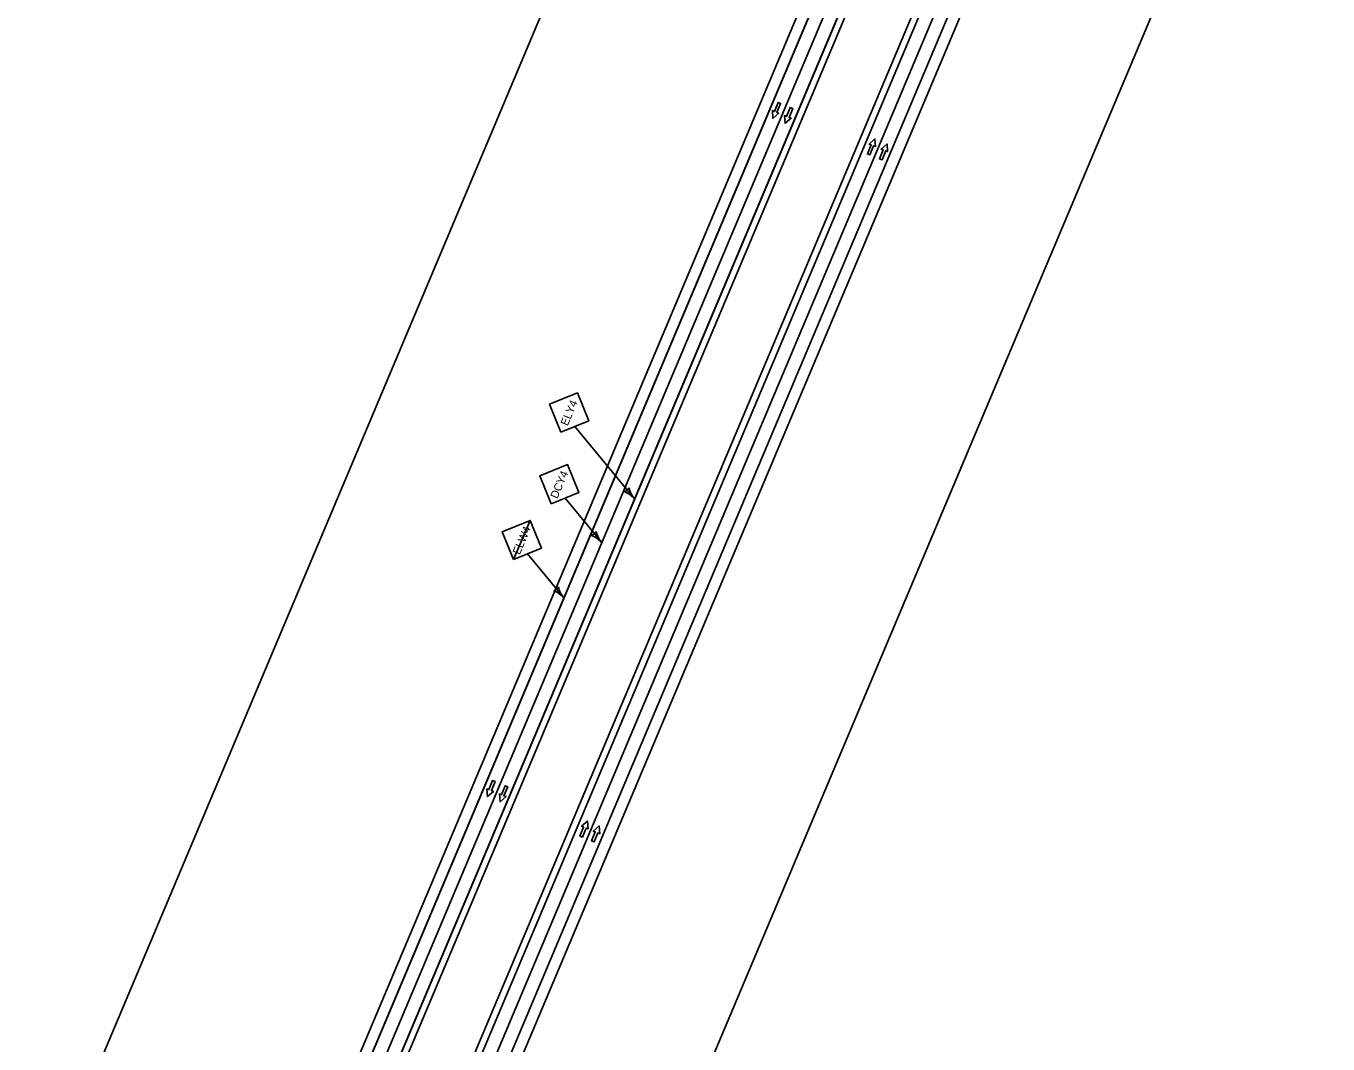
# Model space of a CAD drawing. Extents: x 14104283 to 14129344, y 8637090 to 8673339.
# Drawn here: x 14108941 to 14110109, y 8645697 to 8646611 of the extents above; entities that cross this region are included whole.
import ezdxf

# ---------------------------------------------------------------- set-up
doc = ezdxf.new("R2010")
doc.units = 0
for name, color, linetype in [('Cell', 7, 'Continuous'), ('Default', 7, 'Continuous'), ('dsnNonPlotable', 7, 'Continuous'), ('dsnPaintExistingBrokenLaneLineWhite', 7, 'Continuous'), ('dsnPaintExistingEdgeLineRightWhite', 7, 'Continuous'), ('dsnPaintPlaceBrokenLineWhite', 7, 'Continuous'), ('dsnPaintPlaceEdgeLineLeftYellow', 7, 'Continuous'), ('dsnPaintPlaceEdgeLineRightWhite', 7, 'Continuous'), ('dsnShadingPaved', 7, 'Continuous'), ('dsnStdLabel', 7, 'Continuous'), ('dsnStgShadingPrevPav', 7, 'Continuous')]:
    doc.layers.add(name, color=color, linetype=linetype)

msp = doc.modelspace()

# ---------------------------------------------------------------- linework, layer by layer
at = {"layer": 'Cell'}
for points in [[(14109615.6, 8646542.8), (14109617.9, 8646541.9), (14109614.6, 8646533.8), (14109616.3, 8646533.1), (14109611.1, 8646528.5), (14109610.6, 8646535.5), (14109612.3, 8646534.7)], [(14109626.5, 8646538.4), (14109628.8, 8646537.5), (14109625.5, 8646529.4), (14109627.3, 8646528.7), (14109622, 8646524.1), (14109621.5, 8646531), (14109623.2, 8646530.3)], [(14109698.1, 8646495.8), (14109695.8, 8646496.7), (14109699.1, 8646504.8), (14109697.3, 8646505.5), (14109702.6, 8646510.1), (14109703.1, 8646503.2), (14109701.4, 8646503.9)], [(14109709, 8646491.3), (14109706.7, 8646492.2), (14109710, 8646500.3), (14109708.2, 8646501), (14109713.5, 8646505.6), (14109714, 8646498.7), (14109712.3, 8646499.4)], [(14109359.3, 8645933.9), (14109361.6, 8645933), (14109358.3, 8645924.9), (14109360.1, 8645924.2), (14109354.8, 8645919.6), (14109354.3, 8645926.5), (14109356, 8645925.8)], [(14109370.7, 8645929.3), (14109373, 8645928.3), (14109369.6, 8645920.2), (14109371.4, 8645919.5), (14109366.1, 8645914.9), (14109365.6, 8645921.9), (14109367.3, 8645921.2)], [(14109440, 8645883.1), (14109437.7, 8645884.1), (14109441, 8645892.2), (14109439.3, 8645892.9), (14109444.5, 8645897.5), (14109445.1, 8645890.5), (14109443.3, 8645891.2)], [(14109450.5, 8645878.9), (14109448.2, 8645879.8), (14109451.5, 8645887.9), (14109449.8, 8645888.6), (14109455.1, 8645893.2), (14109455.6, 8645886.2), (14109453.8, 8645886.9)]]:
    msp.add_lwpolyline(points, close=True, dxfattribs=at)
for points in [[(14109612.3, 8646534.7), (14109610.6, 8646535.5), (14109611.1, 8646528.5), (14109616.3, 8646533.1), (14109614.6, 8646533.8), (14109617.9, 8646541.9), (14109615.6, 8646542.8), (14109612.3, 8646534.7)], [(14109623.2, 8646530.3), (14109621.5, 8646531), (14109622, 8646524.1), (14109627.3, 8646528.7), (14109625.5, 8646529.4), (14109628.8, 8646537.5), (14109626.5, 8646538.4), (14109623.2, 8646530.3)], [(14109701.4, 8646503.9), (14109703.1, 8646503.2), (14109702.6, 8646510.1), (14109697.3, 8646505.5), (14109699.1, 8646504.8), (14109695.8, 8646496.7), (14109698.1, 8646495.8), (14109701.4, 8646503.9)], [(14109712.3, 8646499.4), (14109714, 8646498.7), (14109713.5, 8646505.6), (14109708.2, 8646501), (14109710, 8646500.3), (14109706.7, 8646492.2), (14109709, 8646491.3), (14109712.3, 8646499.4)], [(14109356, 8645925.8), (14109354.3, 8645926.5), (14109354.8, 8645919.6), (14109360.1, 8645924.2), (14109358.3, 8645924.9), (14109361.6, 8645933), (14109359.3, 8645933.9), (14109356, 8645925.8)], [(14109367.3, 8645921.2), (14109365.6, 8645921.9), (14109366.1, 8645914.9), (14109371.4, 8645919.5), (14109369.6, 8645920.2), (14109373, 8645928.3), (14109370.7, 8645929.3), (14109367.3, 8645921.2)], [(14109443.3, 8645891.2), (14109445.1, 8645890.5), (14109444.5, 8645897.5), (14109439.3, 8645892.9), (14109441, 8645892.2), (14109437.7, 8645884.1), (14109440, 8645883.1), (14109443.3, 8645891.2)], [(14109453.8, 8645886.9), (14109455.6, 8645886.2), (14109455.1, 8645893.2), (14109449.8, 8645888.6), (14109451.5, 8645887.9), (14109448.2, 8645879.8), (14109450.5, 8645878.9), (14109453.8, 8645886.9)]]:
    msp.add_lwpolyline(points, dxfattribs=at)
at = {"layer": 'Default'}
for points in [[(14118413.2, 8667444.3), (14110818.4, 8649409.2), (14109142.6, 8645431.4)], [(14109164.7, 8645422.1), (14110840.5, 8649399.8), (14118435.4, 8667434.9)]]:
    msp.add_lwpolyline(points, dxfattribs=at)
at = {"layer": 'dsnNonPlotable'}
msp.add_lwpolyline([(14108940.5, 8645523.8), (14109549.1, 8646968.3), (14110014.5, 8646772.2), (14109405.9, 8645327.7)], close=True, dxfattribs=at)
at = {"layer": 'dsnPaintExistingBrokenLaneLineWhite'}
msp.add_line((14109153.7, 8645426.8), (14110829.5, 8649404.5), dxfattribs=at)
at = {"layer": 'dsnPaintExistingEdgeLineRightWhite'}
msp.add_line((14109248.6, 8645386.8), (14110924.4, 8649364.5), dxfattribs=at)
at = {"layer": 'dsnPaintPlaceBrokenLineWhite'}
msp.add_line((14109237.5, 8645391.4), (14110075.4, 8647380.3), dxfattribs=at)
at = {"layer": 'dsnPaintPlaceEdgeLineLeftYellow'}
msp.add_line((14109318.5, 8645614.6), (14110902.3, 8649373.8), dxfattribs=at)
msp.add_lwpolyline([(14111383.6, 8650689.4), (14110840.5, 8649399.8), (14109233.5, 8645585.3)], dxfattribs=at)
at = {"layer": 'dsnPaintPlaceEdgeLineRightWhite'}
msp.add_lwpolyline([(14111344.6, 8650658.6), (14110818.4, 8649409.2), (14109217, 8645608.1)], dxfattribs=at)
at = {"layer": 'dsnShadingPaved'}
for p, q in [((14109258.5, 8645472.2), (14110902.3, 8649373.8)), ((14110924.4, 8649364.5), (14109248.6, 8645386.8))]:
    msp.add_line(p, q, dxfattribs=at)
at = {"layer": 'dsnStdLabel'}
for p, q in [((14109433.2, 8646251.9), (14109486.9, 8646186.8)), ((14109424.4, 8646187.6), (14109457.4, 8646147.6)), ((14109378.2, 8646132.4), (14109393.1, 8646167.6)), ((14109390.7, 8646137.5), (14109423.4, 8646097.9))]:
    msp.add_line(p, q, dxfattribs=at)
for points in [[(14109420.7, 8646246.8), (14109445.7, 8646257), (14109435.5, 8646282), (14109410.5, 8646271.9)], [(14109411.9, 8646182.5), (14109436.9, 8646192.7), (14109426.7, 8646217.7), (14109401.7, 8646207.5)], [(14109378.2, 8646132.4), (14109403.2, 8646142.5), (14109393.1, 8646167.6), (14109368.1, 8646157.4)]]:
    msp.add_lwpolyline(points, close=True, dxfattribs=at)
for centre, radius, start, end in [((14109474.4, 8646201.4), 8.86, 292.8385, 328.307), ((14109469.5, 8646171.9), 22.9, 40.5727, 68.6439), ((14109504.3, 8646201.8), 22.9, 192.5015, 220.5728), ((14109444.8, 8646162.2), 8.86, 292.8385, 328.307), ((14109439.9, 8646132.7), 22.9, 40.5727, 68.6439), ((14109474.8, 8646162.5), 22.9, 192.5015, 220.5728), ((14109410.9, 8646112.5), 8.86, 292.8385, 328.307), ((14109440.8, 8646112.8), 22.9, 192.5015, 220.5728), ((14109406, 8646083), 22.9, 40.5727, 68.6439)]:
    msp.add_arc(centre, radius, start, end, dxfattribs=at)
at = {"layer": 'dsnStgShadingPrevPav'}
for p, q in [((14109133.4, 8645435.3), (14110809.2, 8649413)), ((14110818.4, 8649409.2), (14109142.6, 8645431.4))]:
    msp.add_line(p, q, dxfattribs=at)
for points in [[(14109239, 8645583), (14111389.1, 8650687.1), (14111383.6, 8650689.4), (14109233.5, 8645585.3)], [(14109313, 8645616.9), (14110622.7, 8648725.7), (14110659.7, 8648710.5), (14109349.9, 8645601.4)]]:
    msp.add_lwpolyline(points, close=True, dxfattribs=at)
for points in [[(14111383.6, 8650689.4), (14110840.5, 8649399.8), (14109233.5, 8645585.3)], [(14109217, 8645608.1), (14110818.4, 8649409.2), (14111344.6, 8650658.6)]]:
    msp.add_lwpolyline(points, dxfattribs=at)

# ---------------------------------------------------------------- texts
at = {"layer": 'dsnStdLabel'}
for s, p in [('ELY4', (14109426.7, 8646251.9)), ('DCY4', (14109417.5, 8646186.5)), ('ELW4', (14109383.7, 8646136.2))]:
    msp.add_text(s, height=7.2, rotation=67.1547, dxfattribs=at).set_placement(p)

doc.saveas('drawing.dxf')
